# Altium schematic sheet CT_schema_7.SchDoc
size 274 x 160 mm
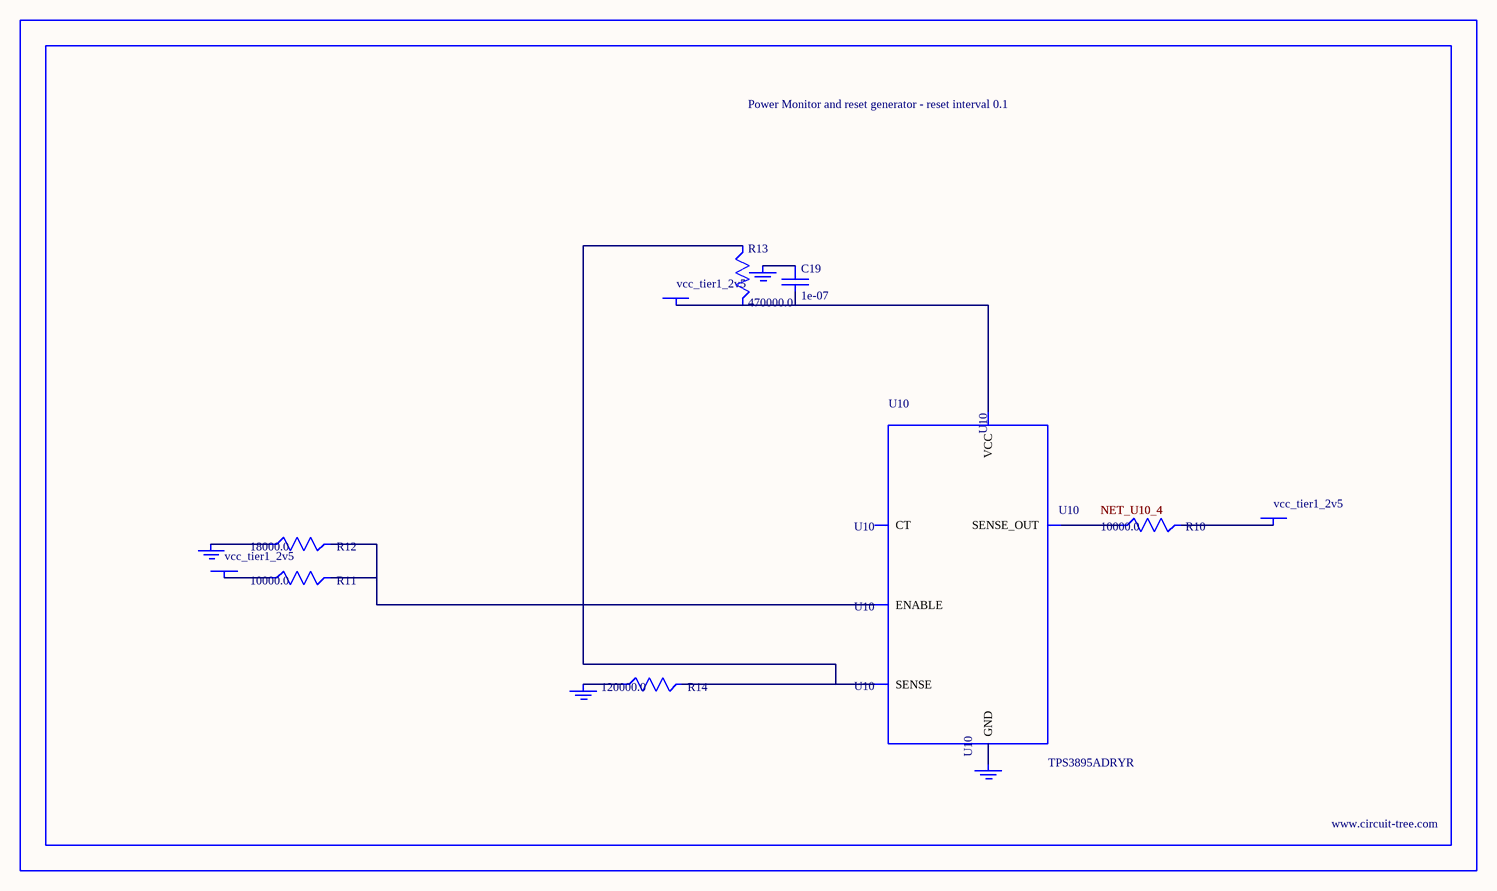
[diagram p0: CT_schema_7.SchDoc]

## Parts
BORDER6  (no value)
C19  1e-07  [C0402]
GND_INSTANCE_6_0  (no value)
GND_INSTANCE_6_1  (no value)
GND_INSTANCE_6_2  (no value)
GND_INSTANCE_6_3  (no value)
POWER_INSTANCE_6_0  vcc_tier1_2v5
POWER_INSTANCE_6_1  vcc_tier1_2v5
POWER_INSTANCE_6_2  vcc_tier1_2v5
R10  10000.0  [R0603]
R11  10000.0  [R0603]
R12  18000.0  [R0603]
R13  470000.0  [R0603]
R14  120000.0  [R0603]
U10  TPS3895ADRYR  [SON-6]

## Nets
NetC19_1: C19.1 GND_INSTANCE_6_2.0(GND)
NetC19_2: C19.2 POWER_INSTANCE_6_2.0(PWR) R13.2 U10.6(VCC)
NetGND_INSTANCE_6_0_0: GND_INSTANCE_6_0.0(GND) R12.1
NetGND_INSTANCE_6_1_0: GND_INSTANCE_6_1.0(GND) R14.1
NetGND_INSTANCE_6_3_0: GND_INSTANCE_6_3.0(GND) U10.2(GND)
NetPOWER_INSTANCE_6_0_0: POWER_INSTANCE_6_0.0(PWR) R11.1
NetPOWER_INSTANCE_6_1_0: POWER_INSTANCE_6_1.0(PWR) R10.2
NetR10_1: R10.1 U10.4(SENSE_OUT)
NetR11_2: R11.2 R12.2 U10.1(ENABLE)
NetR13_1: R13.1 R14.2 U10.3(SENSE)

Not connected (* = marked no-connect by the designer): U10 5(CT)

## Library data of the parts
BORDER6 = BORDER_PAGE6
C19 = C0402C104K3RACTU
GND_INSTANCE_6_0-GND_INSTANCE_6_3 = GND
POWER_INSTANCE_6_0-POWER_INSTANCE_6_2 = PWR
R10 R11 = RC0603JR-0710KL
R12 = RC0603JR-0718KL
R13 = RC0603JR-07470KL
R14 = RC0603JR-07120KL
